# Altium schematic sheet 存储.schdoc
size 297 x 209 mm; Symbol: Drawing-Symbol_A4; @Create Time: 11:16:23; @Update Time: 16:56:06; Border: 1; Width: 1170; Height: 825; Region Start: 1; X Region Count: 6; Y Region Count: 4; Blade Width: 10; Title Block Position: 3; Title Block: 1; @Board Name: Board1; Company: 嘉立创EDA; Version: V1.0; Page Size: A4; @Project Name: stm32f4; @Page Count: 3; @Update Date: 2025-11-07; @Create Date: 2025-10-30; @Schematic Name: Schematic1; @Page No: 2; @Page Name: 存储; Device: Drawing-Symbol_A4
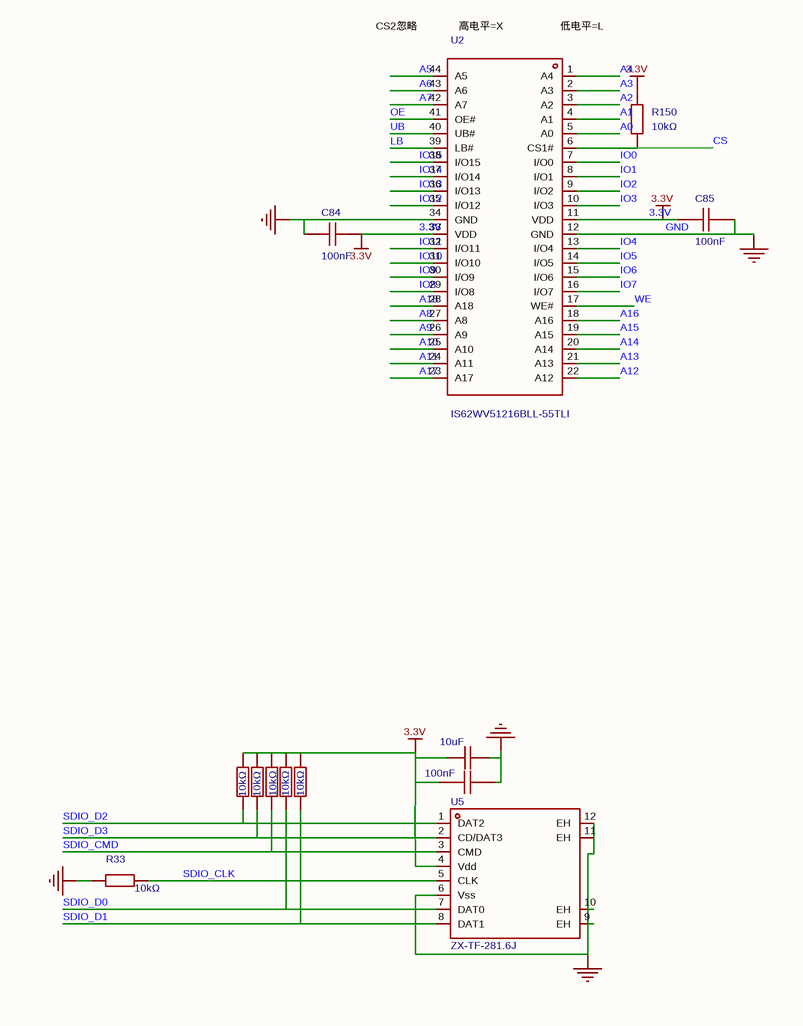
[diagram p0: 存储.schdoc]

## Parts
C3  value 10uF  [C0603]  (hidden comment: 0603X106K100NT)
C4  value 100nF  [C0402]  (hidden comment: CC0402KRX7R7BB104)
C84  100nF  [C0603]
C85  100nF  [C0603]
R28  10kΩ  [R0402]
R29  10kΩ  [R0402]
R30  10kΩ  [R0402]
R31  10kΩ  [R0402]
R32  10kΩ  [R0402]
R33  10kΩ  [R0402]
R150  10kΩ  [R0603]
U2  IS62WV51216BLL-55TLI  [TSOP-44_L18.4-W10.2-P0.80-LS11.8-BL]
U5  ZX-TF-281.6J  [TF-SMD_ZX-TF-281.6J]

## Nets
3.3V: C3.2 C4.2 C84.1 C85.2 R28.2 R29.2 R30.2 R31.2 R32.2 R150.1 U2.11(VDD) U2.33(VDD) U5.4(Vdd)
GND: C3.1 C4.1 C84.2 C85.1 R33.2 U2.12(GND) U2.34(GND) U5.6(Vss) U5.9(EH) U5.10(EH) U5.11(EH) U5.12(EH)
A0: U2.5(A0)
A1: U2.4(A1)
A2: U2.3(A2)
A3: U2.2(A3)
A4: U2.1(A4)
A5: U2.44(A5)
A6: U2.43(A6)
A7: U2.42(A7)
A8: U2.27(A8)
A9: U2.26(A9)
A10: U2.25(A10)
A11: U2.24(A11)
A12: U2.22(A12)
A13: U2.21(A13)
A14: U2.20(A14)
A15: U2.19(A15)
A16: U2.18(A16)
A17: U2.23(A17)
A18: U2.28(A18)
CS: R150.2 U2.6(CS1#)
IO0: U2.7(I/O0)
IO1: U2.8(I/O1)
IO2: U2.9(I/O2)
IO3: U2.10(I/O3)
IO4: U2.13(I/O4)
IO5: U2.14(I/O5)
IO6: U2.15(I/O6)
IO7: U2.16(I/O7)
IO8: U2.29(I/O8)
IO9: U2.30(I/O9)
IO10: U2.31(I/O10)
IO11: U2.32(I/O11)
IO12: U2.35(I/O12)
IO13: U2.36(I/O13)
IO14: U2.37(I/O14)
IO15: U2.38(I/O15)
LB: U2.39(LB#)
OE: U2.41(OE#)
SDIO_CLK: R33.1 U5.5(CLK)
SDIO_CMD: R30.1 U5.3(CMD)
SDIO_D0: R29.1 U5.7(DAT0)
SDIO_D1: R28.1 U5.8(DAT1)
SDIO_D2: R32.1 U5.1(DAT2)
SDIO_D3: R31.1 U5.2(CD/DAT3)
UB: U2.40(UB#)
WE: U2.17(WE#)

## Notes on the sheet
- (near U2) CS2忽略
- (near U2) 高电平=X
- (near U2) 低电平=L

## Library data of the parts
C3 = 0603X106K100NT: 容值:10uF;精度:±10%;额定电压:10V;材质(温度系数):X5R;; Manufacturer: FH(风华); AddInBom: yes; ModelId: ac125912035d415993ca9572d50418b1; ModelName: C0603_L1.6-W0.8-H0.8; ModelTransform: 62.992,31.496,0,0,0,0,0,0,0; Tolerance: ±10%; Voltage Rated: 10V; Temperature Coefficient: X5R
C4 = CC0402KRX7R7BB104: 容值:100nF;精度:±10%;额定电压:16V;材质(温度系数):X7R;; Manufacturer: YAGEO(国巨); AddInBom: yes; ModelId: 36a51122f27c49738f86b3bfa98863e0; ModelName: C0402_L1.0-W0.5-H0.5; ModelTransform: 39.37,19.685,0,0,0,0,0,0,0; Tolerance: ±10%; Voltage Rated: 16V; Temperature Coefficient: X7R
C84 C85 = CC0603KRX7R9BB104: 容值:100nF;精度:±10%;额定电压:50V;材质(温度系数):X7R;; Manufacturer: YAGEO(国巨); AddInBom: yes; ModelId: ac125912035d415993ca9572d50418b1; ModelName: C0603_L1.6-W0.8-H0.8; ModelTransform: 62.992,31.496,0,0,0,0,0,0,0; Tolerance: ±10%; Voltage Rated: 50V; Temperature Coefficient: X7R
R28-R33 = 0402WGF1002TCE: 电阻类型:厚膜电阻;阻值:10kΩ;精度:±1%;功率:62.5mW;工作电压:50V;温度系数:±100ppm/℃;; Manufacturer: UNI-ROYAL(厚声); AddInBom: yes; ModelId: 98c88bc2b9094f218f3a3e30a7012738; ModelName: R0402_L1.0-W0.5-H0.4; ModelTransform: 39.37,19.685,0,0,0,0,0,0,0; Tolerance: ±1%; Power(Watts): 62.5mW; Voltage-Supply(Max): 50V
R150 = 0603WAF1002T5E: 电阻类型:厚膜电阻;阻值:10kΩ;精度:±1%;功率:100mW;最大工作电压:75V;温度系数:±100ppm/℃;; Manufacturer: UNI-ROYAL(厚声); AddInBom: yes; ModelId: fc143cca1e79419f9cd78b61e9279f08; ModelTransform: 31.8897,63.7794,0,90,0,0,0,0,0; Tolerance: ±1%; Power(Watts): 100mW; Overload Voltage (Max): 75V
U2 = IS62WV51216BLL-55TLI: 8-Mbit(512K × 16bit)，并行接口，工作电压：2.5V to 3.6V; Manufacturer: ISSI(美国芯成); AddInBom: yes; ModelId: 560eb33016ce4e308706c564a2ec9c3c; ModelName: TSOP-44_L18.4-W10.2-H1.0-LS11.8-P0.80; ModelTransform: 465.06033,724.408,0,90,0,0,0,-0.0005,0
U5 = ZX-TF-281.6J: 卡连接方式:翻盖式;卡类型:MicroSD卡(TF卡);连接器类型:卡座;本体最大高度:1.8mm;工作温度:-25℃~+85℃;; Manufacturer: Megastar(兆星); AddInBom: yes; Card Connection Mode: 翻盖式; Connector Type: 卡座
